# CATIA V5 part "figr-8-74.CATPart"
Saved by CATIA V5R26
Part number: Part1
Bounding box of the stored display mesh (mm): x -48 to 48, y -106.879 to 106.685, z -32.702 to 29.91
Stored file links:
  D:\_Deepak\CATIA\CATIA V5-6R2016_Deepak\Resources\Part files\Partfiles\c08_catia_v5_6r2016_prt\figr-8-74.CATPart
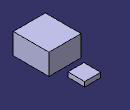
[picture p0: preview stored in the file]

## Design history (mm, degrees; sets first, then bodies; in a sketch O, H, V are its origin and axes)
Body1 (main body)
  Sketch1 on yz-plane, origin (0, 0, 0), H (0, 1, 0), V (0, 0, 1)
    line L1 (-106.8789, 29.9101) -> (0, 29.9101)
    line L2 (0, 29.9101) -> (0, -32.7018)
    line L3 (0, -32.7018) -> (-106.8789, -32.7018)
    line L4 (-106.8789, -32.7018) -> (-106.8789, 29.9101)
    point P3 (0, -32.7018)
    horizontal: L1 H, L3 H
    vertical: L2 V, L4 V
    coincidence: P3 V
  Pad1: profile Sketch1, direction (1, 0, 0), length 48, mirrored extent
  Sketch2 on yz-plane, origin (0, 0, 0), H (0, 1, 0), V (0, 0, 1)
    line L1 (56.3417, 7.481) -> (106.6854, 7.481)
    line L2 (106.6854, 7.481) -> (106.6854, -6.5572)
    line L3 (106.6854, -6.5572) -> (56.3417, -6.5572)
    line L4 (56.3417, -6.5572) -> (56.3417, 7.481)
    horizontal: L1 H, L3 H
    vertical: L2 V, L4 V
  Pad2: profile Sketch2, direction (1, 0, 0), length 48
